Omron CX-Programmer project NuevoProyecto (CX-Programmer 9.50)

# PLC NewPLC1: CQM1 CPU21

## Program P6_2 (no task)
Local symbols
CNT_igual_a_0 15.01 BOOL
CNT_igual_a_1 15.02 BOOL
CNT_igual_a_2 15.03 BOOL
Etapa_0 10.00 BOOL
Etapa_1 10.01 BOOL
Etapa_2 10.02 BOOL
Etapa_3 10.03 BOOL
Etapa_4 10.04 BOOL
Etapa_5 10.05 BOOL
Etapa_6 10.06 BOOL
Etapa_7 10.07 BOOL
FCP 0.04 BOOL
FSS 15.00 BOOL
KB 100.01 BOOL
KS 100.00 BOOL
P1 0.01 BOOL
P2 0.02 BOOL
PB 0.00 BOOL
S 0.03 BOOL

### Section Sección1_Programa_principal
; Programa principal (Etapas 0 ... 7)

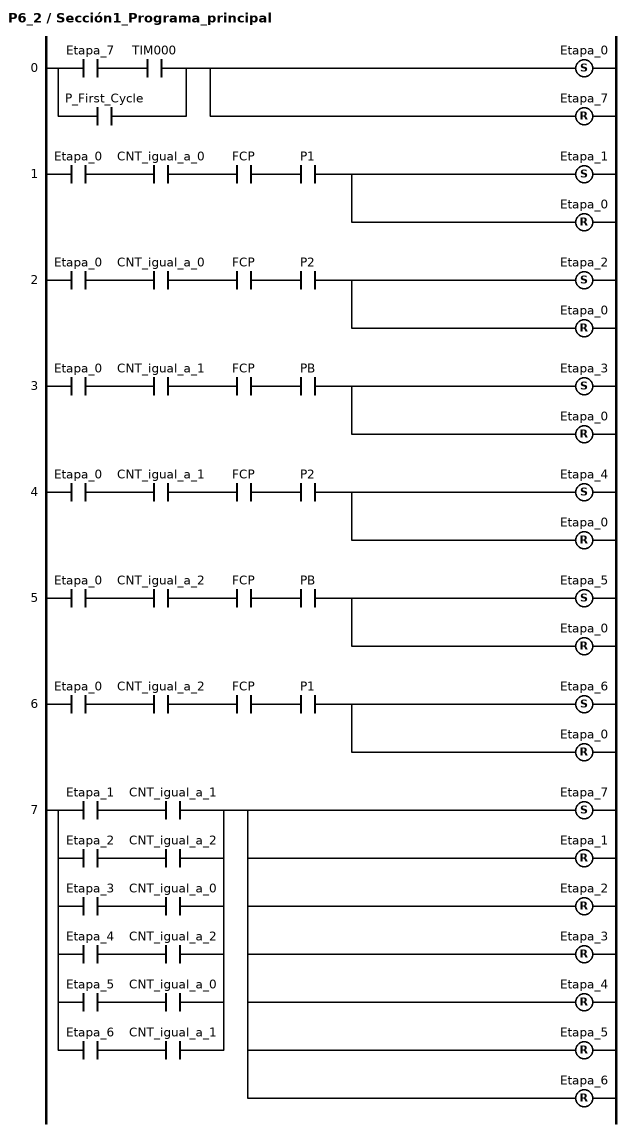
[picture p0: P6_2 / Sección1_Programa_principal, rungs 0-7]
; rung 0
LD Etapa_7
AND TIM000
OR P_First_Cycle
SET Etapa_0
RSET Etapa_7
; rung 1
LD Etapa_0
AND CNT_igual_a_0
AND FCP
AND P1
SET Etapa_1
RSET Etapa_0
; rung 2
LD Etapa_0
AND CNT_igual_a_0
AND FCP
AND P2
SET Etapa_2
RSET Etapa_0
; rung 3
LD Etapa_0
AND CNT_igual_a_1
AND FCP
AND PB
SET Etapa_3
RSET Etapa_0
; rung 4
LD Etapa_0
AND CNT_igual_a_1
AND FCP
AND P2
SET Etapa_4
RSET Etapa_0
; rung 5
LD Etapa_0
AND CNT_igual_a_2
AND FCP
AND PB
SET Etapa_5
RSET Etapa_0
; rung 6
LD Etapa_0
AND CNT_igual_a_2
AND FCP
AND P1
SET Etapa_6
RSET Etapa_0
; rung 7
LD Etapa_1
AND CNT_igual_a_1
LD Etapa_2
AND CNT_igual_a_2
ORLD
LD Etapa_3
AND CNT_igual_a_0
ORLD
LD Etapa_4
AND CNT_igual_a_2
ORLD
LD Etapa_5
AND CNT_igual_a_0
ORLD
LD Etapa_6
AND CNT_igual_a_1
ORLD
SET Etapa_7
RSET Etapa_1
RSET Etapa_2
RSET Etapa_3
RSET Etapa_4
RSET Etapa_5
RSET Etapa_6

### Section Sección2_Temporizador
; Como las etapas E1 y E2 van seguidas se debe resetear el temporizador con TIM0´

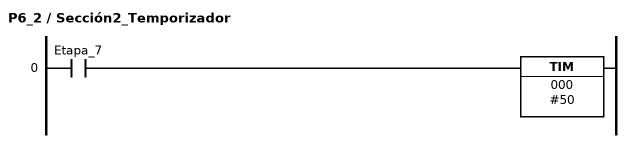
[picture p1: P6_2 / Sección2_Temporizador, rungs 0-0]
; rung 0
LD Etapa_7
TIM 000 #50

### Section Sección3_Contador

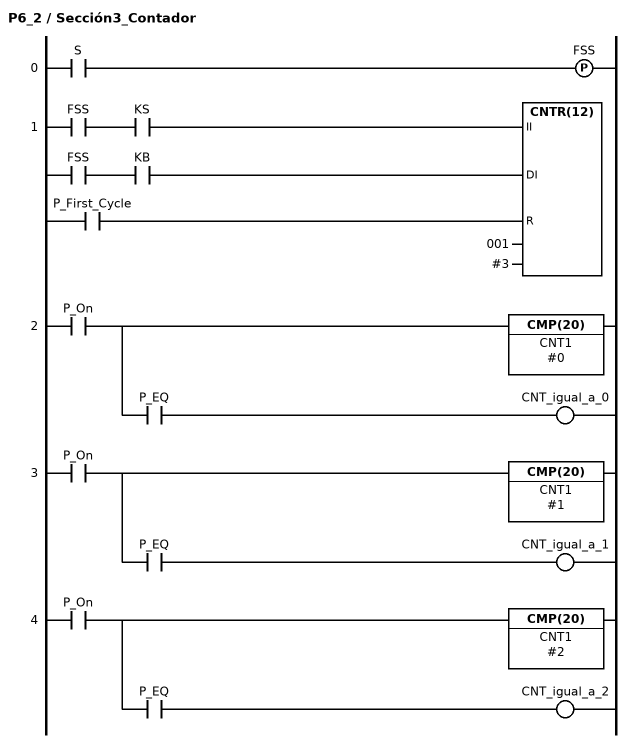
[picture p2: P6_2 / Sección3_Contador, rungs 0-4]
; rung 0
LD S
DIFU(13) FSS
; rung 1
LD FSS
AND KS
LD FSS
AND KB
LD P_First_Cycle
CNTR(12) 001 #3
; rung 2
LD P_On
CMP(20) CNT1 #0
AND P_EQ
OUT CNT_igual_a_0
; rung 3
LD P_On
CMP(20) CNT1 #1
AND P_EQ
OUT CNT_igual_a_1
; rung 4
LD P_On
CMP(20) CNT1 #2
AND P_EQ
OUT CNT_igual_a_2

### Section Sección4_Salidas

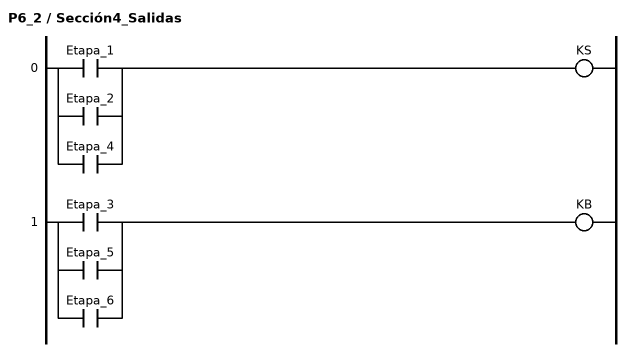
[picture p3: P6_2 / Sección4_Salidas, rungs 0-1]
; rung 0
LD Etapa_1
OR Etapa_2
OR Etapa_4
OUT KS
; rung 1
LD Etapa_3
OR Etapa_5
OR Etapa_6
OUT KB

### Section Sección5_END
; rung 0: Fin de programa
END(01)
